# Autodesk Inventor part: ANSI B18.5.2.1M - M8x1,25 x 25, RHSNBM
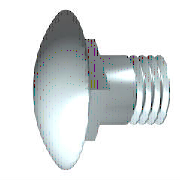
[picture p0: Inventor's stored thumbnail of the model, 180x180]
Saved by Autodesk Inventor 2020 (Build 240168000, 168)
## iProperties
Created: 2019-01
Part Number: ANSI B18.5.2.1M - M8x1,25 x 25, RHSNBM
Material: Acier, doux
Description: Boulon à collet carré, à tête ronde
Document SubType Name: Modeling
Standard: ANSI B18.5.2.1M
Designer: %USERNAME%
Standard Revision: 1996
Standards Organization: ANSI
Language: fr-FR
Size Designation: M8x1,25 x 25
Categories: <MemberInstance><Categories><Category DisplayName="Visserie" InternalName="e4da775c-781d-43d5-af7c-5136215cf5a6" Mnemonic="FSTN"><Category DisplayName="Vis" Int
Density: 7.85 g/cm^3
Appearance: Semi-poli
IsCustomPart: 0
Author: %USERNAME%
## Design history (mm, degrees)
workplane "Work Plane1"
workplane "Work Plane2"
sketch "Sketch4"
  geometry: L1 (4.8, 12.134)-(4.8, 6.067) reference; L2 (-10.76, 6.067)-(30.96, 6.067) reference; L3 (8.5, 10.067)-(25, 10.067) reference; L4 (8.5, 10.067)-(4.8, 10.067); L5 (4.8, 10.067)-(4.8, 12.134); L6 (3.607, 12.134)-(4.8, 10.067); L7 (3.607, 12.134)-(4.8, 12.134)
  constraints: 8 end point, 2 perpendicular, 1 collinear, 1 point on line
  dimensions: "d37" = 30 deg angle of L1 L6
revolve "Revolution4" stored, may be unused: angle "d35" = 90 deg
revolve "Corps" stored, may be unused: angle "d5" = 90 deg
sketch "Esquisse2"
  geometry: L1 (0, -12.6)-(0, 12.6) reference; L2 (12.6, 0)-(-12.6, 0) reference; L3 (-4.29, 4.29)-(4.29, 4.29); L4 (4.29, 4.29)-(4.29, -4.29); L5 (4.29, -4.29)-(-4.29, -4.29); L6 (-4.29, -4.29)-(-4.29, 4.29); L7 (0, 4.29)-(0, -4.29); L8 (-4.29, 0)-(4.29, 0); C1 r 3.52 at (0, 0) reference
  constraints: 12 end point, 4 midpoint, 2 collinear, 2 parallel, 1 horizontal, 1 perpendicular
  dimensions: "d10" = 8.58 distance of L4.end L5.end (= SD2); "d11" = 8.58 distance of L5.end L3.start (= SD2)
extrude "Collet" join sketch "Esquisse2" distance "d12" = 4.8 (= SD); taper "d13" = 0 deg
body "Solid1"
sketch "Esquisse1"
  geometry: L1 (-4.8, 0)-(25, 0); L2 (25, 0)-(25, 4); L3 (0, 3.52)-(0, 9); L4 (0, 9)-(-0.975, 9); L5 (-0.975, 9)-(-0.975, 0); L6 (-11.86, 0)-(31.143, 0) reference; L7 (0, -1.878)-(0, 11.268) reference; L8 (7.733, 3.52)-(8.5, 4); L9 (7.733, 3.52)-(4.8, 3.52); L10 (4.8, 3.52)-(4.8, 3.52); L11 (25, 4)-(8.5, 4); L12 (4.8, 3.52)-(0, 3.52); L13 (4.8, 3.52)-(8, 3.52); A1 r 12.5 centre (7.7, 0) between (-0.975, 9) and (-4.8, 0)
  constraints: 22 end point, 5 parallel, 4 collinear, 2 perpendicular, 2 point on circle, 2 point on line, 1 centre point, 1 horizontal
  dimensions: "d0" = 25 distance between parallel lines of L2 L3 (= NLG); "d1" = 4.8 distance from line of L1.start L3 (= KOH); "d2" = 12.5 radius of A1 (= KR); "d3" = 18 diameter of L4 L1 (= KOD); "d8" = 7.04 diameter of L9 L1 (= BDM); "d9" = 0.76681 horizontal distance of L8.end L8.start (= GAL); "d14" = 4.8 distance between parallel lines of L10 L3 (= SD); "d15" = 7.73319 distance from line of L8.start L3 (= -GEL + NLG - GAL); "d20" = 8 diameter of L11 L1 (= GD)
feature "Filetage" dims "d6" = 16.5 (= GEL), "d7" = 0
chamfer "Chanfrein1" distance "d16" = 2.24 (= -0.5 x SPD + 0.5 x GD); stored, may be unused: second distance "d17" = 0.76681 (= GUL), angle "d31" = 45 deg
other parameters: "GD" = 8 (= NND) [user parameter; used in 3 equation terms], "NLG" = 25 [user parameter; used in 3 equation terms], "GEL" = 16.5 (= NLG - LG) [user parameter; used in 2 equation terms], "KOD" = 18 [user parameter; used in 1 equation term], "KOH" = 4.8 [user parameter; used in 1 equation term], "GAL" = 0.76681 (= 0.61345 x PTC) [user parameter; used in 2 equation terms], "GUL" = 0.76681 (= 0.61345 x PTC) [user parameter; used in 1 equation term], "SPD" = 3.52 (= 0.5 x BDM) [user parameter; used in 1 equation term], "KR" = 12.5 [user parameter; used in 1 equation term], "BDM" = 7.04 [user parameter; used in 2 equation terms], "SD" = 4.8 [user parameter; used in 2 equation terms], "SD2" = 8.58 [user parameter; used in 2 equation terms], "d4" = 8 (= GD), "d19" = 0, "d32" = 0, "d33" = 0, "KKR" = 0.8 [user parameter], "THREADDIA" = 8 [user parameter; used in 1 equation term], "TOA" = 30 deg [user parameter], "ANG" = 30 deg [user parameter], "TPU" = 8 (computed from PTC) [user parameter], "PTC" = 1.25 [user parameter; used in 4 equation terms], "NND" = 8 [user parameter; used in 1 equation term], "LG" = 8.5 [user parameter; used in 1 equation term], "GD1" = 6.46637 (= THREADDIA - 1.2269 x PTC) [user parameter]
